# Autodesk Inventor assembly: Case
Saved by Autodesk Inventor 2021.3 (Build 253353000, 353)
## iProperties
Created: 2021-12
Part Number: Case
Document SubType Name: Assembly
Designer: Administrator
Title: Case v26
Author: Administrator
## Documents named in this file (3)
- c:\worker\convert-fusion-r08\tmp\job-1\42\output\files\5687be83-607c-4978-9340-54991ac6dc59\d0e0bd2a-b3a7-46f8-b739-8f50d766ced6.iam
- c:\worker\convert-fusion-r08\tmp\job-1\42\output\files\5687be83-607c-4978-9340-54991ac6dc59\board v1.iam
- c:\worker\convert-fusion-r08\tmp\job-1\42\output\files\5687be83-607c-4978-9340-54991ac6dc59\Part36.ipt
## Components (2 placed, 2 different names)
1. board v1:1 [sub-assembly]
2. Part36
